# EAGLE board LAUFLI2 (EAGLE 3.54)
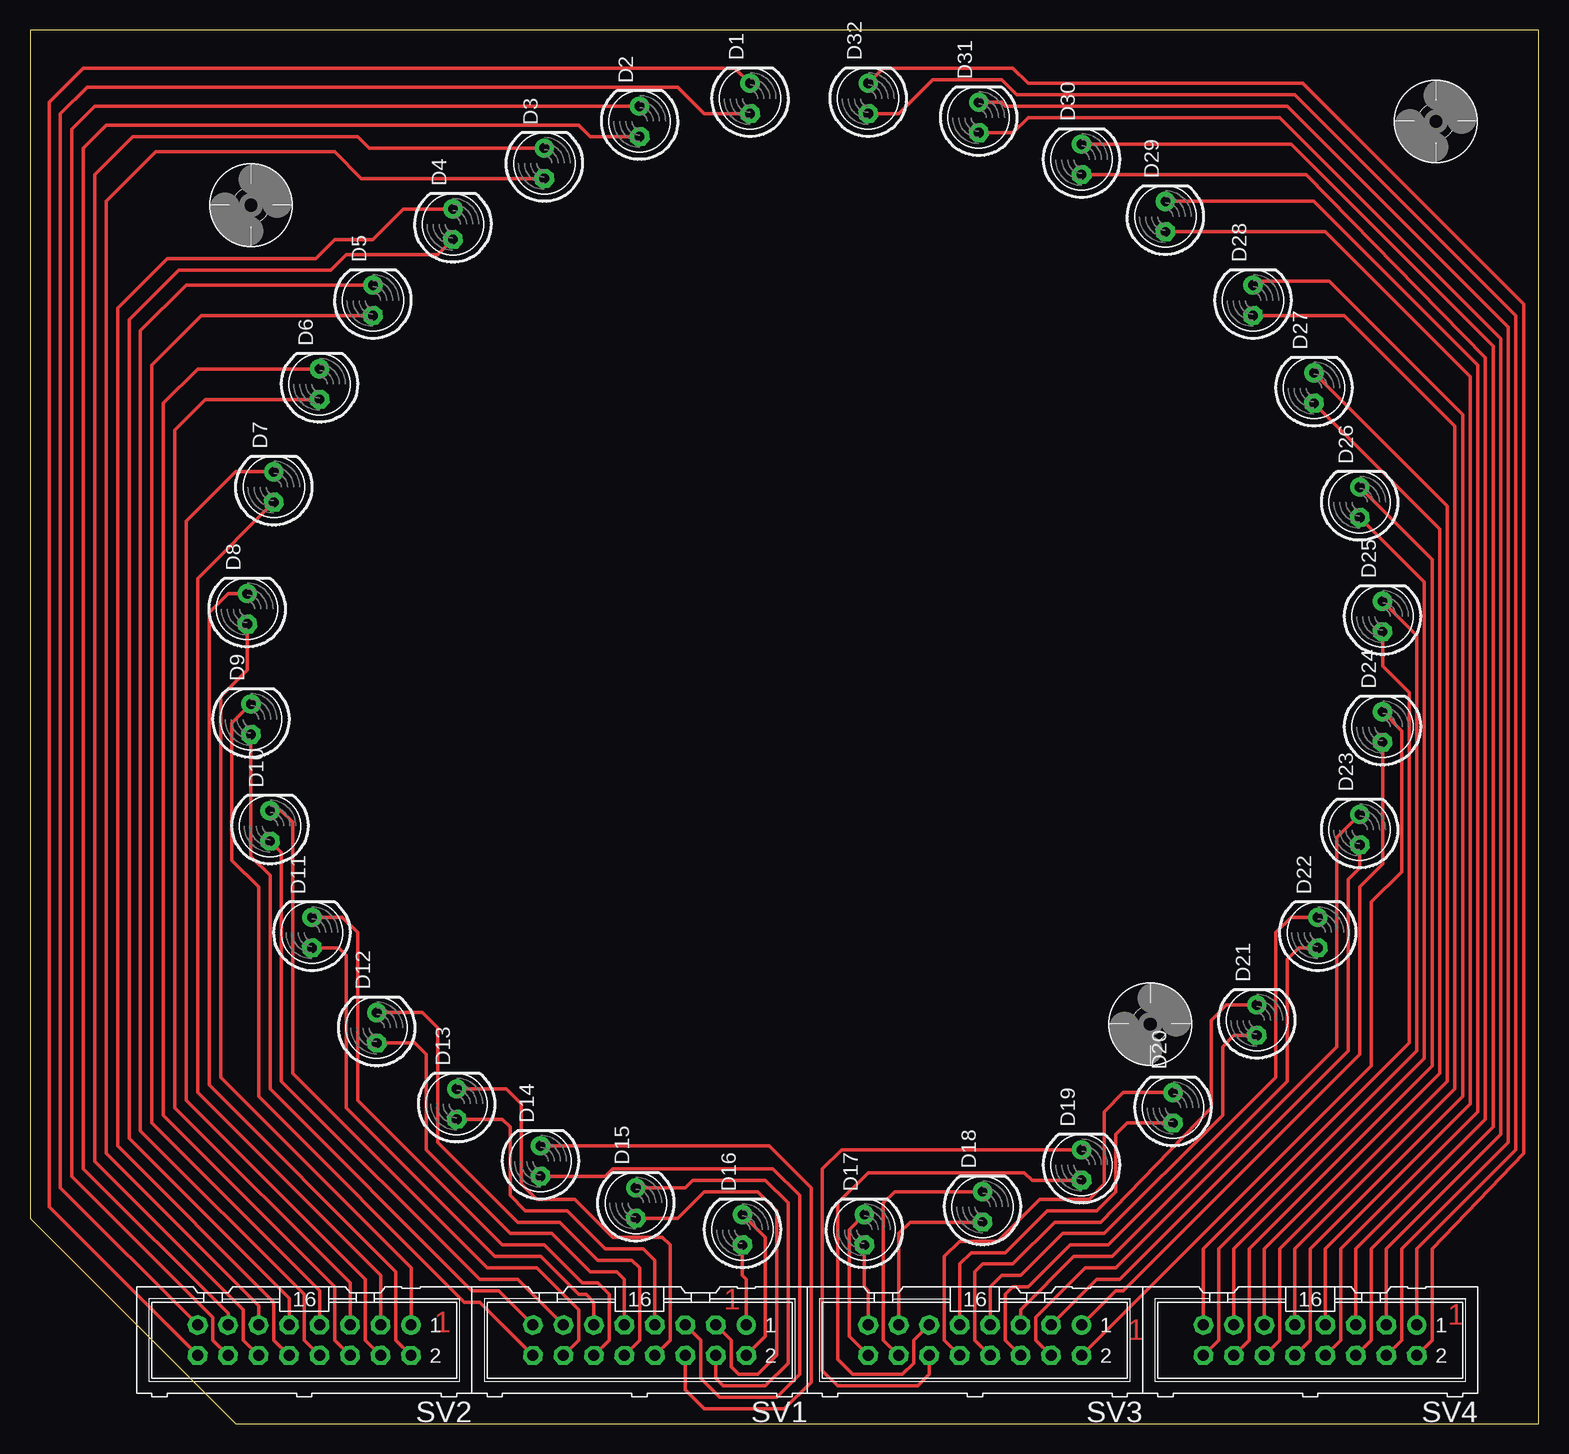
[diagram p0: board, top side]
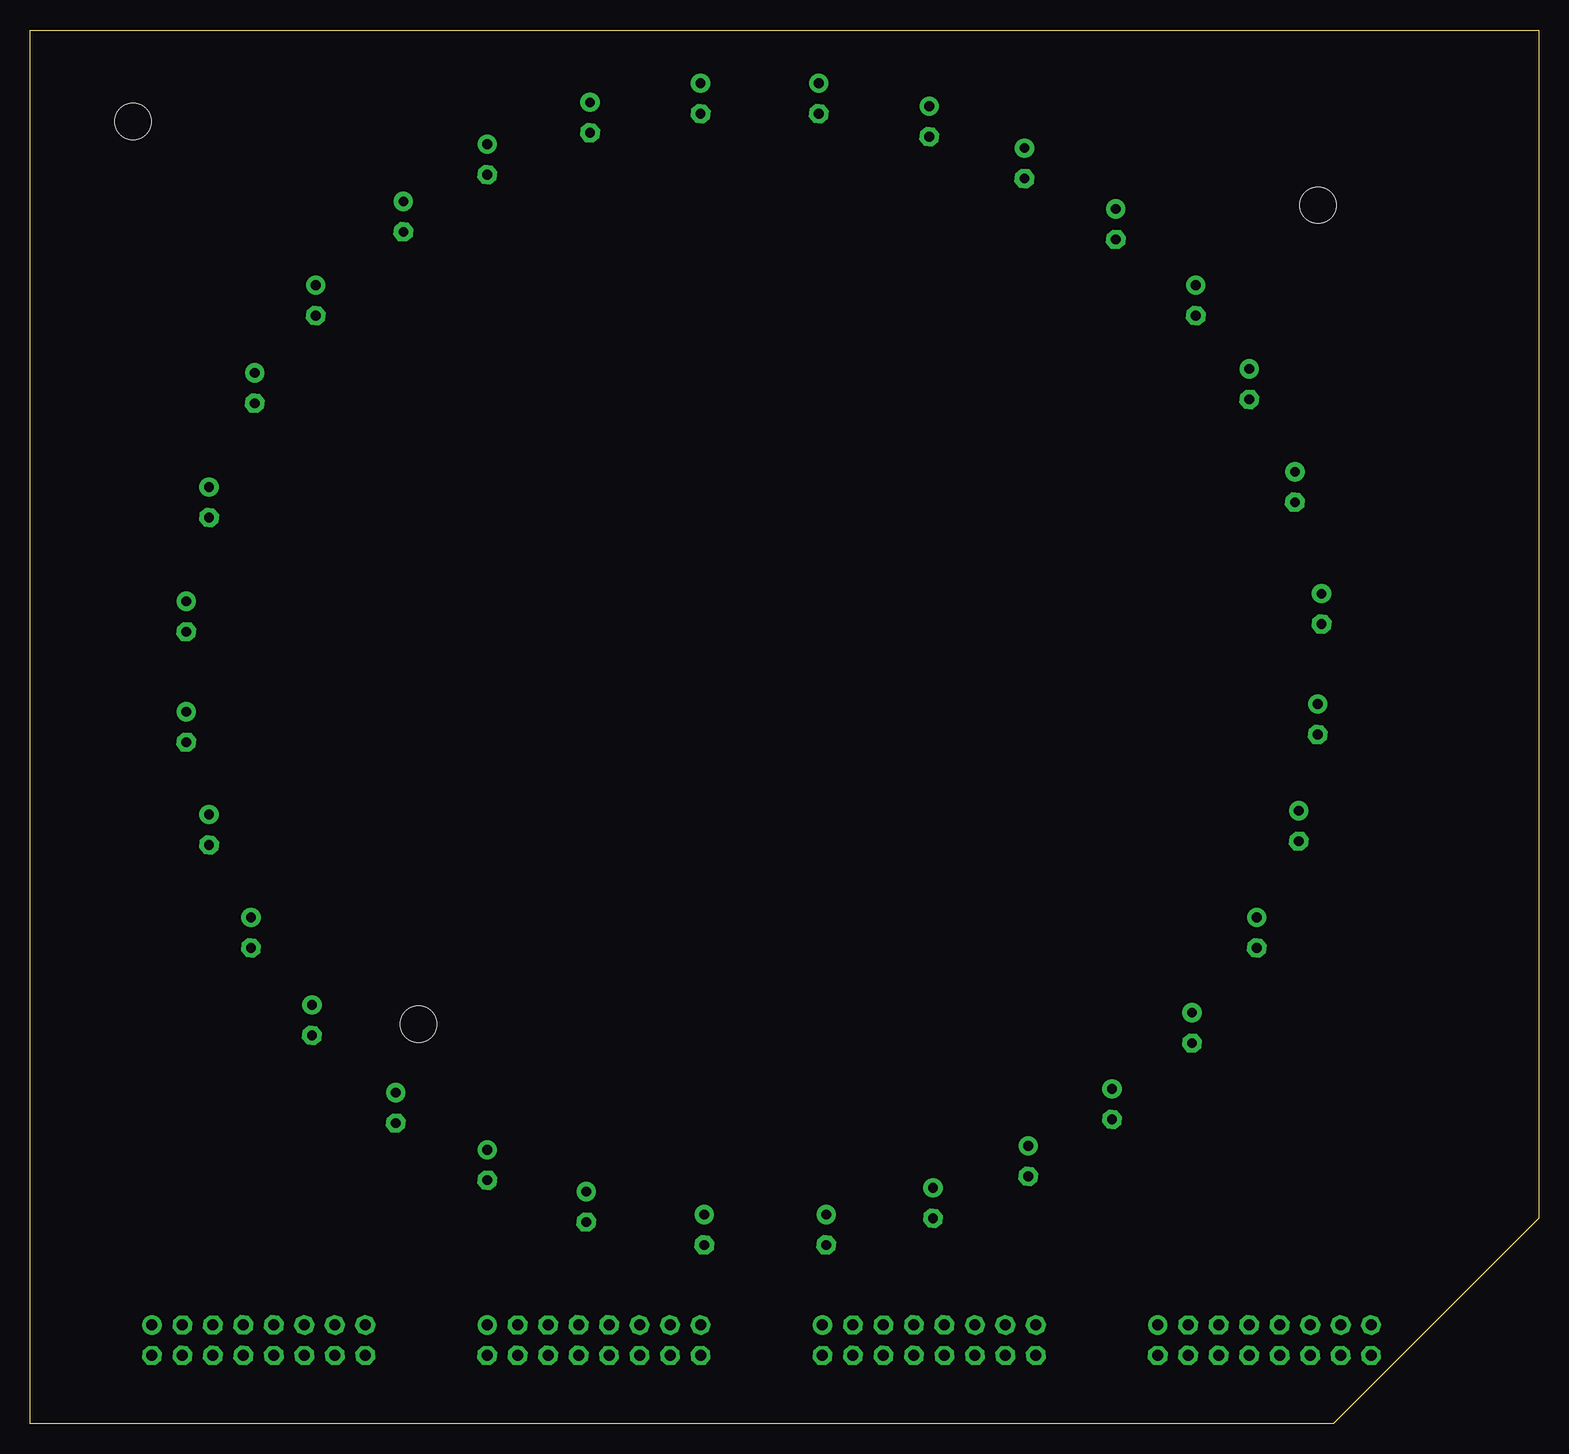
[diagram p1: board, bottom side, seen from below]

Size 125.73 x 116.2 mm. Coordinates in mm from the lower left corner, seen from the top.
Outline: 5.71,11.43 17.14,0 125.73,0 125.73,116.2 0,116.2 0,17.14 5.71,11.43
Copper layers used: Top

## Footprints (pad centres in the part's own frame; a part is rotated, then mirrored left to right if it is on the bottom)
D5 = drill 0.813 pad 1.6 octagon:  -1.27,0 | drill 0.813 pad 1.6 round:  1.27,0
16 = drill 0.914 pad 1.6 round:  -8.89,-1.27 | drill 0.914 pad 1.6 octagon:  -8.89,1.27;  -6.35,-1.27;  -6.35,1.27;  -3.81,-1.27;  -3.81,1.27;  -1.27,-1.27;  -1.27,1.27;  1.27,-1.27;  1.27,1.27;  3.81,-1.27;  3.81,1.27;  6.35,-1.27;  6.35,1.27;  8.89,-1.27;  8.89,1.27
3,0 = hole 3.023: 0,0

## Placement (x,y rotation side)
D1  [D5]  60.01,110.49 90 top
D2  [D5]  50.8,108.58 90 top
D3  [D5]  42.86,105.09 90 top
D4  [D5]  35.24,100.01 90 top
D5  [D5]  28.57,93.66 90 top
D6  [D5]  24.13,86.68 90 top
D7  [D5]  20.32,78.1 90 top
D8  [D5]  18.1,67.94 90 top
D9  [D5]  18.41,58.74 90 top
D10  [D5]  20,49.85 90 top
D11  [D5]  23.49,40.96 90 top
D12  [D5]  28.89,33.02 90 top
D13  [D5]  35.56,26.67 90 top
D14  [D5]  42.54,21.91 90 top
D15  [D5]  50.48,18.41 90 top
D16  [D5]  59.37,16.19 90 top
D17  [D5]  69.53,16.19 90 top
D18  [D5]  79.38,18.1 90 top
D19  [D5]  87.63,21.59 90 top
D20  [D5]  95.25,26.35 90 top
D21  [D5]  102.23,33.66 90 top
D22  [D5]  107.32,40.96 90 top
D23  [D5]  110.81,49.53 90 top
D24  [D5]  112.71,58.1 90 top
D25  [D5]  112.71,67.31 90 top
D26  [D5]  110.81,76.83 90 top
D27  [D5]  107,86.36 90 top
D28  [D5]  101.92,93.66 90 top
D29  [D5]  94.62,100.65 90 top
D30  [D5]  87.63,105.41 90 top
D31  [D5]  79.06,108.9 90 top
D32  [D5]  69.85,110.49 90 top
SV1  [16]  50.8,6.99 180 top
SV2  [16]  22.86,6.99 180 top
SV3  [16]  78.74,6.99 180 top
SV4  [16]  106.68,6.99 180 top
U$3  [3,0]  18.41,101.6 0 top
U$4  [3,0]  93.34,33.34 0 top
U$5  [3,0]  117.16,108.58 0 top

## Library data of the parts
D1-D32 = LED
SV1-SV4 = CON-ML
U$3-U$5 = HOLES

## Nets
N$1: D1. SV2.
N$2: D2. SV2.
N$3: D3. SV2.
N$4: D4. SV2.
N$5: D5. SV2.
N$6: D6. SV2.
N$7: D7. SV2.
N$8: D8. SV2.
N$9: D9. SV1.
N$10: D10. SV1.
N$11: D11. SV1.
N$12: D12. SV1.
N$13: D13. SV1.
N$14: D14. SV1.
N$15: D15. SV1.
N$16: D16. SV1.
N$17: D9. SV1.
N$18: D10. SV1.
N$19: D11. SV1.
N$20: D12. SV1.
N$37: D13. SV1.
N$38: D14. SV1.
N$39: D15. SV1.
N$40: D16. SV1.
N$41: D1. SV2.
N$42: D2. SV2.
N$43: D3. SV2.
N$44: D4. SV2.
N$45: D5. SV2.
N$46: D6. SV2.
N$47: D7. SV2.
N$48: D8. SV2.
N$49: D17. SV3.
N$50: D18. SV3.
N$51: D19. SV3.
N$52: D20. SV3.
N$53: D21. SV3.
N$54: D22. SV3.
N$55: D23. SV3.
N$56: D24. SV3.
N$57: D17. SV3.
N$58: D18. SV3.
N$59: D19. SV3.
N$60: D20. SV3.
N$61: D21. SV3.
N$62: D22. SV3.
N$63: D23. SV3.
N$64: D24. SV3.
N$65: D25. SV4.
N$66: D26. SV4.
N$67: D27. SV4.
N$68: D28. SV4.
N$69: D29. SV4.
N$70: D30. SV4.
N$71: D31. SV4.
N$72: D32. SV4.
N$73: D25. SV4.
N$74: D26. SV4.
N$75: D27. SV4.
N$76: D28. SV4.
N$77: D29. SV4.
N$78: D30. SV4.
N$79: D31. SV4.
N$80: D32. SV4.

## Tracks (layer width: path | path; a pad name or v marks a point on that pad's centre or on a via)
N$1
  Top 0.305: SV2. 1.59,18.1 1.59,110.17 4.44,113.03 58.74,113.03 D1.
N$2
  Top 0.305: 16.51,5.72 15.24,6.99 15.24,8.89 3.49,20.64 3.49,107.95 5.4,109.85 D2.
N$3
  Top 0.305: 19.05,5.72 17.78,6.99 17.78,9.52 5.4,21.91 5.4,104.14 8.57,107.31 27.3,107.31 28.26,106.36 D3.
N$4
  Top 0.305: 21.59,5.72 20.32,6.99 20.32,10.16 7.3,23.18 7.3,93.03 11.43,97.15 23.81,97.15 25.4,98.74 28.57,98.74 31.11,101.28 D4.
N$5
  Top 0.305: 24.13,5.72 22.86,6.99 22.86,10.8 9.21,24.45 9.21,91.12 13.02,94.93 D5.
N$6
  Top 0.305: 26.67,5.72 25.4,6.99 25.4,11.43 11.11,25.72 11.11,85.09 13.97,87.95 D6.
N$7
  Top 0.305: 29.21,5.72 27.94,6.99 27.94,12.07 13.02,26.99 13.02,75.25 17.14,79.38 D7.
N$8
  Top 0.305: 31.75,5.72 30.48,6.99 30.48,12.7 14.92,28.26 14.92,67.63 16.51,69.21 D8.
N$9
  Top 0.305: SV1. 37.46,10.16 36.2,10.16 19.05,27.3 19.05,44.77 16.83,46.99 16.83,58.42 D9.
N$10
  Top 0.305: 44.45,5.72 45.72,6.99 45.72,9.52 42.23,13.02 38.1,13.02 21.91,29.21 21.91,50.16 20.95,51.12 D10.
N$11
  Top 0.305: 46.99,5.72 48.26,6.99 48.26,10.8 47.31,11.75 46.04,11.75 42.86,14.92 39.37,14.92 27.3,26.99 27.3,40.96 26.03,42.23 D11.
N$12
  Top 0.305: 49.53,5.72 50.8,6.99 50.8,13.02 50.16,13.65 47.31,13.65 44.13,16.83 40.64,16.83 33.97,23.5 33.97,33.02 32.7,34.29 D12.
N$13
  Top 0.305: D13. 39.69,27.94 40.96,26.67 40.96,20 42.23,18.73 45.4,18.73 48.58,15.56 52.7,15.56 53.34,14.92 53.34,6.99 52.07,5.72
N$14
  Top 0.305: D14. 61.59,23.18 65.09,19.69 65.09,3.49 62.87,1.27 56.2,1.27 54.61,2.86 54.61,5.72
N$15
  Top 0.305: D15. 54.61,19.69 55.24,20.32 61.28,20.32 63.18,18.41 63.18,5.08 61.28,3.17 57.79,3.17 57.15,3.81 57.15,5.72
N$16
  Top 0.305: D16. 61.28,15.56 61.28,7.3 59.69,5.72
N$17
  Top 0.305: 41.91,8.25 39.05,11.11 36.83,11.11 20,27.94 20,45.72 18.41,47.31 18.41,57.47
N$18
  Top 0.305: 44.45,8.25 40.64,12.07 37.46,12.07 20.95,28.57 20.95,47.62 20,48.58
N$19
  Top 0.305: 46.99,8.25 46.99,10.16 46.35,10.8 45.72,10.8 42.54,13.97 38.73,13.97 26.35,26.35 26.35,39.05 25.72,39.69 23.49,39.69
N$20
  Top 0.305: 28.89,31.75 32.07,31.75 33.02,30.8 33.02,22.86 40,15.88 43.5,15.88 44.13,15.24 46.67,12.7 48.9,12.7 49.53,12.07 49.53,8.25
N$21  (via drill 0.3 pad 2.18)
  other vias: 18.41,101.6
N$22  (via drill 0.3 pad 2.18)
  other vias: 117.16,108.58
N$23  (via drill 0.3 pad 2.18)
  other vias: 93.34,33.34
N$37
  Top 0.305: 35.56,25.4 39.37,25.4 40,24.77 40,19.05 41.27,17.78 44.77,17.78 47.94,14.61 51.12,14.61 52.07,13.65 52.07,8.25
N$38
  Top 0.305: 54.61,8.25 55.88,6.99 55.88,3.81 57.47,2.22 62.23,2.22 64.14,4.13 64.14,19.05 61.91,21.27 48.58,21.27 47.94,20.64 42.54,20.64
N$39
  Top 0.305: 57.15,8.25 58.42,6.99 58.42,4.76 59.05,4.13 60.64,4.13 62.23,5.72 62.23,17.78 60.64,19.37 56.2,19.37 53.98,17.14 50.48,17.14
N$40
  Top 0.305: 59.37,14.92 59.37,12.38 59.69,12.07 59.69,8.25
N$41
  Top 0.305: 13.97,8.25 2.54,19.69 2.54,109.22 4.76,111.44 53.98,111.44 56.2,109.22 60.01,109.22
N$42
  Top 0.305: 16.51,8.25 16.51,9.21 4.44,21.27 4.44,106.36 6.35,108.27 45.72,108.27 46.67,107.31 50.8,107.31
N$43
  Top 0.305: 19.05,8.25 19.05,9.84 6.35,22.54 6.35,101.92 10.48,106.04 25.4,106.04 27.62,103.82 42.86,103.82
N$44
  Top 0.305: 21.59,8.25 21.59,10.48 8.26,23.81 8.26,92.07 12.38,96.2 25.08,96.2 26.35,97.47 33.97,97.47 35.24,98.74
N$45
  Top 0.305: 24.13,8.25 24.13,11.11 10.16,25.08 10.16,88.27 14.29,92.39 28.57,92.39
N$46
  Top 0.305: 26.67,8.25 26.67,11.75 12.06,26.35 12.06,82.87 14.6,85.41 24.13,85.41
N$47
  Top 0.305: 29.21,8.25 29.21,12.38 13.97,27.62 13.97,70.48 20.32,76.83
N$48
  Top 0.305: 31.75,8.25 31.75,13.02 15.87,28.89 15.87,60.64 18.1,62.87 18.1,66.67
N$49
  Top 0.305: SV3. 68.26,7.3 68.26,16.19 D17.
N$50
  Top 0.305: 72.39,5.72 71.12,6.99 71.12,18.41 72.07,19.37 D18.
N$51
  Top 0.305: 74.93,5.72 74.93,4.13 73.98,3.17 67.31,3.17 66.04,4.45 66.04,21.27 67.63,22.86 D19.
N$52
  Top 0.305: 77.47,5.72 76.2,6.99 76.2,13.97 77.47,15.24 80.65,15.24 84.14,18.73 88.27,18.73 89.54,20 89.54,26.04 91.12,27.62 D20.
N$53
  Top 0.305: 80.01,5.72 78.74,6.99 78.74,12.7 79.38,13.34 81.92,13.34 85.41,16.83 89.22,16.83 98.43,26.35 98.43,33.66 99.7,34.93 D21.
N$54
  Top 0.305: 82.55,5.72 81.28,6.99 81.28,10.8 81.92,11.43 83.19,11.43 86.68,14.92 89.85,14.92 103.82,28.89 103.82,40.96 105.09,42.23 D22.
N$55
  Top 0.305: 85.09,5.72 83.82,6.99 83.82,8.89 87.95,13.02 90.49,13.02 108.9,31.43 108.9,48.9 D23.
N$56
  Top 0.305: 87.63,5.72 111.76,29.84 111.76,43.5 114.3,46.04 114.3,57.79 D24.
N$57
  Top 0.305: 69.85,8.25 69.85,11.11 69.53,11.43 69.53,14.92
N$58
  Top 0.305: 72.39,8.25 72.39,15.88 73.34,16.83 79.38,16.83
N$59
  Top 0.305: 74.93,8.25 73.66,6.99 73.66,5.08 72.71,4.13 68.58,4.13 67.31,5.4 67.31,18.41 69.85,20.96 82.87,20.96 83.5,20.32 87.63,20.32
N$60
  Top 0.305: 77.47,8.25 77.47,13.34 78.42,14.29 81.28,14.29 84.77,17.78 88.9,17.78 90.49,19.37 90.49,24.13 91.44,25.08 95.25,25.08
N$61
  Top 0.305: 102.23,32.38 100.33,32.38 99.38,31.43 99.38,25.72 89.54,15.88 86.04,15.88 82.55,12.38 80.96,12.38 80.01,11.43 80.01,8.25
N$62
  Top 0.305: 82.55,8.25 82.55,9.52 87,13.97 90.17,13.97 104.78,28.57 104.78,38.73 105.73,39.69 107.32,39.69
N$63
  Top 0.305: 85.09,8.25 88.9,12.07 90.81,12.07 109.86,31.12 109.86,45.4 110.81,46.36 110.81,48.26
N$64
  Top 0.305: 87.63,8.25 90.49,11.11 91.12,11.11 110.81,30.8 110.81,44.77 112.71,46.67 112.71,56.83
N$65
  Top 0.305: SV4. 99.06,6.99 99.06,14.61 115.57,31.12 115.57,65.72 D25.
N$66
  Top 0.305: 100.33,5.72 101.6,6.99 101.6,14.61 116.84,29.84 116.84,72.07 D26.
N$67
  Top 0.305: 102.87,5.72 104.14,6.99 104.14,14.61 118.11,28.57 118.11,76.52 D27.
N$68
  Top 0.305: 105.41,5.72 106.68,6.99 106.68,14.61 119.38,27.3 119.38,84.14 108.27,95.25 102.23,95.25 D28.
N$69
  Top 0.305: 107.95,5.72 109.22,6.99 109.22,14.61 120.65,26.04 120.65,88.27 107,101.92 D29.
N$70
  Top 0.305: 110.49,5.72 111.76,6.99 111.76,14.61 121.92,24.77 121.92,89.85 105.09,106.68 D30.
N$71
  Top 0.305: 113.03,5.72 114.3,6.99 114.3,14.61 123.19,23.5 123.19,91.44 104.78,109.85 81.28,109.85 80.96,110.17 D31.
N$72
  Top 0.305: 115.57,5.72 116.84,6.99 116.84,14.61 124.46,22.54 124.46,93.34 106.05,111.76 83.19,111.76 81.92,113.03 71.12,113.03 D32.
N$73
  Top 0.305: 97.79,8.25 97.79,14.61 114.94,31.75 114.94,60.96 112.71,63.18 112.71,66.04
N$74
  Top 0.305: 100.33,8.25 100.33,14.61 116.2,30.48 116.2,70.17 110.81,75.56
N$75
  Top 0.305: 102.87,8.25 102.87,14.61 117.48,29.21 117.48,74.61 107,85.09
N$76
  Top 0.305: 105.41,8.25 105.41,14.61 118.75,27.94 118.75,83.18 109.54,92.39 101.92,92.39
N$77
  Top 0.305: 107.95,8.25 107.95,14.61 120.02,26.67 120.02,87.31 107.95,99.38 94.62,99.38 94.3,99.06
N$78
  Top 0.305: 110.49,8.25 110.49,14.61 121.29,25.4 121.29,88.9 106.36,104.14 87.63,104.14
N$79
  Top 0.305: 113.03,8.25 113.03,14.61 122.55,24.13 122.55,90.49 104.14,108.9 83.19,108.9 81.92,107.63 79.06,107.63
N$80
  Top 0.305: 115.57,8.25 115.57,14.61 123.83,22.86 123.83,92.39 105.41,110.81 82.23,110.81 80.96,112.08 75.25,112.08 72.39,109.22 69.85,109.22

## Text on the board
Top: 1 | 1 | 1 | 1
